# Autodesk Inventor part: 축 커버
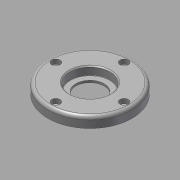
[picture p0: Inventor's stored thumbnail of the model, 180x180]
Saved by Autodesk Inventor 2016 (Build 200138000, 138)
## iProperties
Created: 2015-10
Part Number: 축 커버
Document SubType Name: Modeling
Designer: mdu
Density: 7.86 g/cm^3
Material: 강철, 연강
Appearance: 강철
Mass: 322.464 g
Surface Area: 133.703 cm^2
Volume: 41.026 cm^3
Author: mdu
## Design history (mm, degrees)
sketch "스케치1"
  geometry: C1 r 40 at (0, 0) reference; C2 r 26 at (0, 0) reference; 1 further point
  node "참조1"
  node "참조2"
extrude "돌출1" new body sketch "스케치1" distance "d0" = 10; taper "d1" = 0 deg
extrude "돌출2" join sketch "스케치1" distance "d2" = 3; taper "d3" = 0 deg
hole "구멍1" diameter "d6" = 27; stored, may be unused: countersink angle "d10" = 90 deg, drill point angle "d12" = 118 deg; dims "d4" = 10, "d5" = 10, "d7" = 6, "d8" = 38, "d9" = 8, "d11" = 8
sketch "스케치2"
  geometry: C1 r 20 at (0, 0); 1 further point
  constraints: 1 centre point, 1 coincident
  dimensions: "d13" = 40 diameter of C1
extrude "돌출3" cut sketch "스케치2" distance "d14" = 3; taper "d15" = 0 deg
sketch "스케치3"
  geometry: C1 r 1.621 at (0, 32.5) reference; 1 further point
hole "구멍2" sketch "스케치3" at (0, 32.5) diameter "d16" = 4.5; stored, may be unused: countersink angle "d20" = 90 deg, drill point angle "d22" = 118 deg; dims "d17" = 6, "d18" = 8, "d19" = 4.4, "d21" = 8
fillet "모깎기1" dims "d26" = 3, "d27" = 0.3
chamfer "모따기1" distance "d28" = 1; stored, may be unused: second distance "d29" = 2, angle "d30" = 45 deg
node "솔리드1"
pattern_circular "원형 패턴1" dims angle "d24" = 360 deg
node "참조3"
